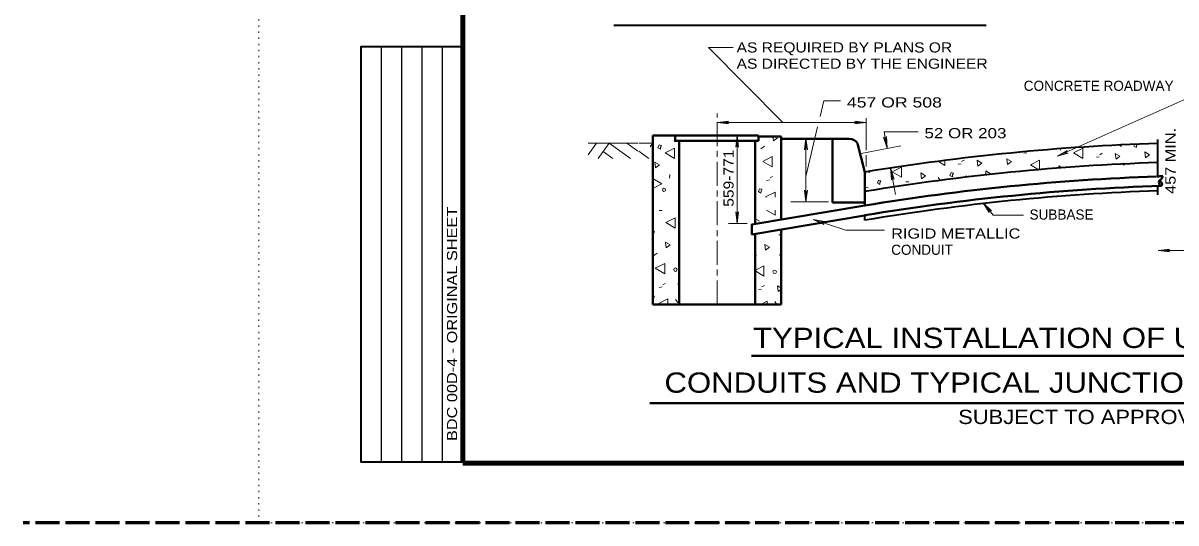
# Model space of a CAD drawing. Extents: x 312583 to 312854, y 144419 to 144597.
# Drawn here: x 312583.5 to 312670, y 144418.6 to 144456.1 of the extents above; entities that cross this region are included whole.
import ezdxf
from ezdxf.enums import TextEntityAlignment as Align

# ---------------------------------------------------------------- set-up
doc = ezdxf.new("R2010")
doc.units = 0
doc.header["$LTSCALE"] = 0.3
doc.header["$PDMODE"] = 32
doc.header["$PDSIZE"] = 0.15
for name, pattern in [('DOTTED', [1.5, 0.3, -1.2]), ('LONG_DASH_SHORT_DASH', [9.9, 6, -1.2, 1.5, -1.2]), ('LONG_DASHED', [7.5, 6, -1.5])]:
    doc.linetypes.add(name, pattern=pattern)
for name, color, linetype, lineweight in [('1', 7, 'Continuous', 40), ('2', 7, 'Continuous', 13), ('63', 7, 'DOTTED', 13)]:
    doc.layers.add(name, color=color, linetype=linetype, lineweight=lineweight)

msp = doc.modelspace()

# ---------------------------------------------------------------- linework, layer by layer
at = {"layer": '1', "lineweight": 25}
for p, q in [((312610.4087, 144423.1446), (312610.4087, 144454.3629)), ((312611.9315, 144423.1446), (312611.9315, 144454.3629)), ((312613.4543, 144423.1446), (312613.4543, 144454.3629)), ((312614.9772, 144423.1446), (312614.9772, 144454.3629))]:
    msp.add_line(p, q, dxfattribs=at)
at = {"layer": '1', "lineweight": 13}
msp.add_line((312648.1308, 144440.5671), (312645.2405, 144440.5671), dxfattribs=at)
at = {"layer": '1'}
msp.add_line((312630.7658, 144434.9934), (312640.3952, 144434.9934), dxfattribs=at)
at = {"layer": '1', "lineweight": 158}
msp.add_line((312616.5, 144423.0846), (312849, 144423.0846), dxfattribs=at)
at = {"layer": '1', "linetype": 'LONG_DASHED', "lineweight": 60}
msp.add_line((312851.75, 144418.5846), (312583.526, 144418.5846), dxfattribs=at)
at = {"layer": '1', "lineweight": 158}
msp.add_lwpolyline([(312616.5, 144423.1446), (312616.5, 144585.0846), (312849, 144585.0846)], dxfattribs=at)
at = {"layer": '1', "lineweight": 35}
msp.add_lwpolyline([(312616.5, 144423.1446), (312608.8858, 144423.1446), (312608.8858, 144454.3629), (312616.5, 144454.3629)], dxfattribs=at)
at = {"layer": '2', "lineweight": 35}
for p, q in [((312627.8321, 144455.9615), (312655.7549, 144455.9615)), ((312668.6315, 144444.6304), (312668.6315, 144447.3751)), ((312668.6315, 144443.2121), (312668.6315, 144443.8637)), ((312646.6512, 144441.3184), (312646.6512, 144441.6787))]:
    msp.add_line(p, q, dxfattribs=at)
at = {"layer": '2'}
for p, q in [((312634.9442, 144454.2751), (312636.7918, 144454.2751)), ((312634.9442, 144454.2751), (312640.5102, 144448.6554)), ((312672.5568, 144451.2237), (312661.0875, 144446.1177)), ((312643.5845, 144450.2807), (312643.3085, 144449.0924)), ((312644.8418, 144450.2807), (312643.5845, 144450.2807)), ((312635.5805, 144448.6554), (312636.4545, 144448.7627)), ((312646.7585, 144448.6554), (312635.5805, 144448.6554)), ((312635.5805, 144448.6554), (312636.4545, 144448.5481)), ((312636.4545, 144448.7627), (312636.1708, 144448.6554)), ((312636.4545, 144448.5481), (312636.1708, 144448.6554)), ((312645.8845, 144448.7627), (312646.1605, 144448.6554)), ((312646.7585, 144448.6554), (312645.8845, 144448.7627)), ((312645.8845, 144448.5481), (312646.1605, 144448.6554)), ((312646.7585, 144448.6554), (312645.8845, 144448.5481)), ((312646.7585, 144446.5624), (312646.7585, 144448.9774)), ((312631.7625, 144447.5974), (312631.9772, 144447.6357)), ((312637.0908, 144447.6664), (312636.9835, 144446.7924)), ((312637.0908, 144447.6664), (312637.1982, 144446.7924)), ((312637.0908, 144443.0357), (312637.0908, 144447.6664)), ((312639.7742, 144447.6051), (312639.8202, 144447.2677)), ((312643.1245, 144448.3257), (312642.2505, 144444.5921)), ((312648.1078, 144447.9424), (312648.3302, 144446.7157)), ((312648.1078, 144447.9424), (312650.6685, 144447.9424)), ((312648.2765, 144447.5897), (312648.2305, 144447.2984)), ((312648.3302, 144446.7157), (312648.2765, 144447.5897)), ((312626.5338, 144447.0914), (312625.9205, 144446.2251)), ((312625.9205, 144447.0914), (312629.6465, 144447.0914)), ((312627.4768, 144447.0914), (312626.6642, 144445.9414)), ((312629.0868, 144445.9414), (312627.4768, 144447.0914)), ((312629.6465, 144446.4857), (312628.8032, 144447.0914)), ((312629.7002, 144447.0914), (312630.7735, 144447.0914)), ((312630.7428, 144447.0684), (312630.5588, 144446.8154)), ((312636.9835, 144446.7924), (312637.0908, 144447.0684)), ((312637.1982, 144446.7924), (312637.0908, 144447.0684)), ((312639.1455, 144446.8691), (312638.8695, 144446.6697)), ((312642.2505, 144447.4614), (312642.1432, 144446.5951)), ((312642.1432, 144446.5951), (312642.2505, 144446.8711)), ((312642.2505, 144447.4614), (312642.3578, 144446.5951)), ((312642.2505, 144447.4134), (312642.2505, 144442.6907)), ((312642.3578, 144446.5951), (312642.2505, 144446.8711)), ((312646.2525, 144446.3094), (312649.3575, 144446.9074)), ((312648.0695, 144447.5514), (312648.2305, 144447.2984)), ((312648.3302, 144446.7157), (312648.0695, 144447.5514)), ((312661.3865, 144446.7004), (312661.3328, 144446.5777)), ((312667.0445, 144446.9227), (312667.1058, 144447.0377)), ((312627.7605, 144445.9414), (312627.0322, 144446.4627)), ((312630.4592, 144445.9414), (312629.7002, 144446.4857)), ((312646.7585, 144445.3434), (312646.7585, 144446.1867)), ((312658.5805, 144446.3477), (312658.8028, 144446.3631)), ((312661.0798, 144446.1254), (312661.8465, 144446.5471)), ((312661.0798, 144446.1254), (312661.9232, 144446.3477)), ((312661.8465, 144446.5471), (312661.6318, 144446.3477)), ((312661.9232, 144446.3477), (312661.6318, 144446.3477)), ((312664.0315, 144446.0411), (312664.2462, 144446.0794)), ((312664.2845, 144446.2327), (312664.4762, 144446.3401)), ((312646.9962, 144444.9754), (312647.0192, 144444.9754)), ((312648.9665, 144443.2351), (312648.5985, 144445.2361)), ((312648.5985, 144445.2361), (312648.6522, 144444.3544)), ((312648.5985, 144445.2361), (312648.8592, 144444.4004)), ((312652.1788, 144445.7191), (312652.6542, 144445.4277)), ((312652.6542, 144445.4277), (312652.6542, 144445.7804)), ((312653.6662, 144445.5197), (312653.8808, 144445.5581)), ((312653.9192, 144445.7191), (312654.1108, 144445.8187)), ((312655.7285, 144445.0137), (312655.7362, 144444.7071)), ((312656.1502, 144444.7607), (312655.7285, 144445.0137)), ((312632.0078, 144444.4617), (312632.0462, 144444.7454)), ((312639.2912, 144444.3007), (312639.5212, 144444.3391)), ((312639.5518, 144444.5001), (312639.7435, 144444.5997)), ((312648.6522, 144444.3544), (312648.7058, 144444.6534)), ((312648.8592, 144444.4004), (312648.7058, 144444.6534)), ((312649.7408, 144444.1857), (312649.9708, 144444.2011)), ((312652.1558, 144444.5307), (312652.3092, 144444.3237)), ((312654.8775, 144444.6151), (312654.9005, 144444.5921)), ((312642.1432, 144443.5647), (312642.2505, 144443.2811)), ((312642.2505, 144442.6907), (312642.1432, 144443.5647)), ((312642.3578, 144443.5647), (312642.2505, 144443.2811)), ((312642.2505, 144442.6907), (312642.3578, 144443.5647)), ((312646.6665, 144443.8177), (312646.9195, 144443.7487)), ((312637.0908, 144442.0774), (312637.0908, 144443.0357)), ((312641.1082, 144442.6907), (312643.9372, 144442.6907)), ((312656.2882, 144441.6941), (312655.5292, 144442.6217)), ((312655.5292, 144442.6217), (312655.9892, 144441.8857)), ((312655.5292, 144442.6217), (312656.1578, 144442.0161)), ((312631.2335, 144442.0314), (312631.4558, 144442.0391)), ((312636.9835, 144441.9317), (312637.0908, 144441.6557)), ((312637.0908, 144441.0654), (312636.9835, 144441.9317)), ((312637.0908, 144441.0654), (312637.0908, 144442.0774)), ((312637.1982, 144441.9317), (312637.0908, 144441.6557)), ((312637.0908, 144441.0654), (312637.1982, 144441.9317)), ((312639.2835, 144442.0774), (312639.9352, 144441.6941)), ((312639.9352, 144441.6941), (312639.9352, 144442.0774)), ((312655.9892, 144441.8857), (312655.8972, 144442.1694)), ((312656.1578, 144442.0161), (312655.8972, 144442.1694)), ((312656.2882, 144441.6941), (312658.5652, 144441.6941)), ((312636.4392, 144441.0654), (312637.8498, 144441.0654)), ((312638.7698, 144441.2341), (312638.5322, 144441.3797)), ((312645.2405, 144440.5671), (312642.7948, 144441.3797)), ((312642.7948, 144441.3797), (312643.5845, 144441.0041)), ((312642.7948, 144441.3797), (312643.6535, 144441.2111)), ((312643.6535, 144441.2111), (312643.3545, 144441.1957)), ((312643.5845, 144441.0041), (312643.3545, 144441.1957)), ((312640.2188, 144440.2067), (312640.3338, 144440.2144)), ((312668.6698, 144439.0414), (312669.5362, 144439.1487)), ((312668.6698, 144439.0414), (312669.5362, 144438.9341)), ((312668.9305, 144439.0414), (312670.9008, 144439.0414)), ((312669.5362, 144439.1487), (312669.2602, 144439.0414)), ((312669.5362, 144438.9341), (312669.2602, 144439.0414)), ((312631.0878, 144438.8421), (312630.8195, 144438.6427)), ((312638.5398, 144438.6734), (312638.3865, 144438.5661)), ((312640.2725, 144438.7347), (312640.3492, 144438.5891)), ((312631.5018, 144436.4731), (312631.6858, 144436.5727)), ((312638.9462, 144436.3044), (312639.1455, 144436.4041)), ((312631.2412, 144436.2737), (312631.4635, 144436.3121)), ((312632.7132, 144436.1281), (312632.7285, 144436.1357)), ((312638.6932, 144436.1051), (312638.9155, 144436.1434)), ((312640.1652, 144435.9594), (312640.3568, 144436.1051)), ((312632.4525, 144435.3691), (312632.6442, 144435.1314)), ((312639.9122, 144435.2004), (312640.0655, 144434.9934))]:
    msp.add_line(p, q, dxfattribs=at)
at = {"layer": '2', "linetype": 'LONG_DASH_SHORT_DASH'}
for p, q in [((312635.5805, 144434.9934), (312635.5805, 144449.3224)), ((312635.5192, 144447.9731), (312635.5192, 144447.9807))]:
    msp.add_line(p, q, dxfattribs=at)
at = {"layer": '2', "lineweight": 40}
for p, q in [((312632.4448, 144447.6664), (312630.7658, 144447.6664)), ((312632.4448, 144447.2677), (312632.4448, 144447.6664)), ((312640.3952, 144447.6051), (312638.6778, 144447.6051)), ((312638.6778, 144447.2677), (312638.6778, 144447.6051)), ((312640.4488, 144447.4134), (312640.8092, 144447.4134)), ((312640.7478, 144447.4134), (312645.4935, 144447.4134)), ((312644.2438, 144442.6447), (312644.2438, 144447.4134)), ((312646.6512, 144444.9294), (312646.1222, 144447.0684)), ((312646.6512, 144442.4147), (312646.6512, 144444.9294)), ((312646.6512, 144442.6447), (312644.2438, 144442.6447)), ((312646.7892, 144441.7017), (312638.1795, 144440.2527)), ((312638.4325, 144434.9934), (312638.4325, 144440.2374)), ((312640.3952, 144434.9934), (312640.3952, 144440.6207)), ((312638.1714, 144431.1251), (312710.7439, 144431.1251)), ((312718.444, 144427.5906), (312630.5394, 144427.5906))]:
    msp.add_line(p, q, dxfattribs=at)
for points in [[(312630.7658, 144434.9934), (312630.7658, 144443.0357), (312630.7658, 144447.6664)], [(312638.6778, 144447.6664), (312635.7108, 144447.6664), (312632.4448, 144447.6664)], [(312640.3952, 144441.3567), (312640.3952, 144443.0357), (312640.3952, 144447.6051)], [(312638.6778, 144447.2677), (312635.7108, 144447.2677), (312632.4448, 144447.2677)], [(312632.7285, 144434.9934), (312632.7285, 144443.0357), (312632.7285, 144447.2677)], [(312638.4325, 144441.0271), (312638.4325, 144443.0357), (312638.4325, 144447.2677)], [(312646.6665, 144442.4147), (312638.1795, 144440.9887), (312638.1795, 144440.2527)]]:
    msp.add_lwpolyline(points, dxfattribs=at)
at = {"layer": '2'}
for points in [[(312639.8202, 144447.2677), (312640.1192, 144447.4901), (312639.9122, 144447.6051)], [(312665.7028, 144446.9687), (312665.7028, 144446.9534), (312665.8868, 144446.8384), (312665.8868, 144446.9764)], [(312666.9065, 144447.0301), (312666.8452, 144446.8691), (312667.0445, 144446.7694), (312667.0445, 144446.9227)], [(312656.6408, 144446.2634), (312656.6792, 144446.2481), (312656.6792, 144446.2711)], [(312659.7765, 144445.0981), (312659.7765, 144445.8264), (312659.0788, 144445.4737), (312659.7228, 144445.0904)], [(312661.4708, 144445.2361), (312661.2178, 144445.3894), (312661.2408, 144445.2131)], [(312663.5638, 144445.4047), (312663.5025, 144445.4201), (312663.4872, 144445.3971)], [(312630.7658, 144443.7027), (312631.4328, 144444.0401), (312630.7658, 144444.4387)], [(312654.3025, 144444.5154), (312654.2948, 144444.6534), (312653.9345, 144444.4694)], [(312639.9352, 144443.0357), (312639.9352, 144443.4267), (312639.2222, 144443.0741), (312639.2835, 144443.0357)], [(312630.8042, 144440.3371), (312630.8808, 144440.4674), (312630.7658, 144440.4981)], [(312630.7658, 144440.1991), (312630.8118, 144440.1837), (312630.8042, 144440.3371)], [(312632.7285, 144436.5267), (312632.6595, 144436.5574), (312632.7132, 144436.1281)], [(312640.3568, 144436.2431), (312640.1115, 144436.3887), (312640.1652, 144435.9594)], [(312630.8195, 144435.4764), (312630.8962, 144435.6067), (312630.7658, 144435.6451)], [(312630.7658, 144435.3537), (312630.8195, 144435.3154), (312630.8195, 144435.4764)], [(312631.8775, 144434.9934), (312631.8775, 144435.3997), (312631.1722, 144435.0471), (312631.2565, 144434.9934)], [(312639.3295, 144434.9934), (312639.3295, 144435.2311), (312638.8618, 144434.9934)]]:
    msp.add_lwpolyline(points, dxfattribs=at)
for points in [[(312631.3408, 144446.8001), (312631.4098, 144446.9304), (312631.2335, 144446.9764), (312631.1415, 144446.7541), (312631.3408, 144446.6391)], [(312632.3912, 144445.9491), (312632.3912, 144446.7234), (312631.6858, 144446.3707)], [(312663.0195, 144445.9491), (312663.0195, 144446.7234), (312662.3142, 144446.3707)], [(312639.7052, 144445.3127), (312639.7052, 144446.0871), (312639.0075, 144445.7344)], [(312657.3615, 144445.4891), (312657.6605, 144445.7114), (312657.3078, 144445.9184)], [(312665.5035, 144445.8877), (312665.7948, 144446.1177), (312665.4422, 144446.3247)], [(312667.7268, 144446.0027), (312668.0258, 144446.2251), (312667.6732, 144446.4397)], [(312630.9728, 144445.2514), (312631.2565, 144445.4661), (312630.9038, 144445.6807)], [(312649.4188, 144444.5384), (312649.4188, 144445.3051), (312648.7135, 144444.9524)], [(312655.1382, 144445.3741), (312655.4295, 144445.5964), (312655.0845, 144445.8111)], [(312647.7858, 144444.1474), (312647.8625, 144444.2701), (312647.6862, 144444.3237), (312647.6018, 144444.0937), (312647.7935, 144443.9864)], [(312650.9138, 144444.4311), (312651.2052, 144444.6534), (312650.8525, 144444.8681)], [(312653.2445, 144444.7224), (312653.3135, 144444.8527), (312653.1372, 144444.9064), (312653.0452, 144444.6764), (312653.2368, 144444.5691)], [(312638.8772, 144443.5034), (312638.9462, 144443.6337), (312638.7698, 144443.6797), (312638.6855, 144443.4574), (312638.8695, 144443.3424)], [(312632.4372, 144440.7281), (312632.4372, 144441.5024), (312631.7318, 144441.1497)], [(312631.7702, 144439.2407), (312632.0615, 144439.4631), (312631.7088, 144439.6701)], [(312639.2222, 144439.0721), (312639.5135, 144439.2944), (312639.1532, 144439.5014)], [(312631.6552, 144437.2857), (312631.6552, 144438.0601), (312630.9498, 144437.7074)], [(312639.0995, 144437.1171), (312639.0995, 144437.8914), (312638.4018, 144437.5464)]]:
    msp.add_lwpolyline(points, close=True, dxfattribs=at)
for centre, radius in [((312631.5937, 144443.591), 0.1178), ((312632.4552, 144437.6059), 0.1301), ((312639.9056, 144437.4361), 0.1301)]:
    msp.add_circle(centre, radius, dxfattribs=at)
at = {"layer": '2', "lineweight": 40}
for centre, radius, start, end in [((312645.4947, 144446.6602), 0.7515, 33.19305, 89.95496), ((312674.349, 144275.8703), 168.8299, 91.97148, 99.43765), ((312674.349, 144275.8703), 168.8299, 91.81461, 91.95231), ((312674.349, 144275.8703), 168.1094, 91.86362, 99.47856)]:
    msp.add_arc(centre, radius, start, end, dxfattribs=at)
at = {"layer": '2', "lineweight": 35}
for radius, start, end in [(171.3086, 91.91193, 99.29981), (169.8675, 91.92816, 99.37931), (167.7491, 91.94859, 99.50295)]:
    msp.add_arc((312674.349, 144275.8703), radius, start, end, dxfattribs=at)
at = {"layer": '2'}
msp.add_arc((312674.349, 144275.8703), 169.8675, 92.07399, 99.29981, dxfattribs=at)
at = {"layer": '2', "lineweight": 40}
msp.add_spline([(312668.9995, 144444.6151), (312668.8922, 144444.4004), (312668.7465, 144444.2701), (312668.7312, 144444.0707), (312668.8845, 144443.8867), (312668.9535, 144443.9864), (312668.8845, 144444.1781), (312668.7848, 144444.3314)], degree=3, dxfattribs=at)
at = {"layer": '2'}
for p in [(312632.4448, 144447.2677), (312646.9962, 144444.9754), (312666.0938, 144445.5274)]:
    msp.add_point(p, dxfattribs=at)
at = {"layer": '63'}
msp.add_line((312601.2, 144418.5846), (312601.2, 144596.7846), dxfattribs=at)
msp.add_lwpolyline([(312601.2, 144418.5846), (312853.5, 144418.5846), (312853.5, 144596.7846)], dxfattribs=at)

# ---------------------------------------------------------------- texts
at = {"layer": '1', "width": 1.2}
msp.add_text('BDC 00D-4 - ORIGINAL SHEET', height=0.7614, rotation=90, dxfattribs=at).set_placement((312616.0832, 144424.7374))
at = {"layer": '2'}
for s, width, p in [('AS REQUIRED BY PLANS OR ', 1.15, (312637.0448, 144453.9061)), ('AS DIRECTED BY THE ENGINEER', 1.15, (312637.0448, 144452.6861)), ('457 OR 508 ', 1.3, (312645.3191, 144449.7778)), ('52 OR 203', 1.25, (312651.1382, 144447.4702)), ('RIGID METALLIC ', 1.2, (312648.6387, 144439.9355))]:
    msp.add_text(s, height=0.76, dxfattribs=dict(at, width=width)).set_placement(p)
for s, p in [('CONCRETE ROADWAY', (312658.5831, 144451.0256)), ('SUBBASE', (312659.0178, 144441.3598)), ('CONDUIT', (312648.6387, 144438.7155))]:
    msp.add_text(s, height=0.76, dxfattribs=at).set_placement(p)
for s, width, p in [('457 MIN.', 1.2, (312669.9665, 144443.2927)), ('559-771', 1.15, (312636.821, 144442.3251))]:
    msp.add_text(s, height=0.76, rotation=90, dxfattribs=dict(at, width=width)).set_placement(p)
at = {"layer": '2', "width": 1.15}
for s, height, p in [('TYPICAL INSTALLATION OF UNDER ROADWAY RIGID METALLIC', 1.52, (312674.183, 144431.7205)), ('CONDUITS AND TYPICAL JUNCTION BOXES (457 BY 914 MM) INSTALLATION', 1.52, (312674.431, 144428.3625)), ('SUBJECT TO APPROVAL OF THE ENGINEER', 1.07, (312671.2173, 144426.012))]:
    msp.add_text(s, height=height, dxfattribs=at).set_placement(p, align=Align.CENTER)

doc.saveas('drawing.dxf')
